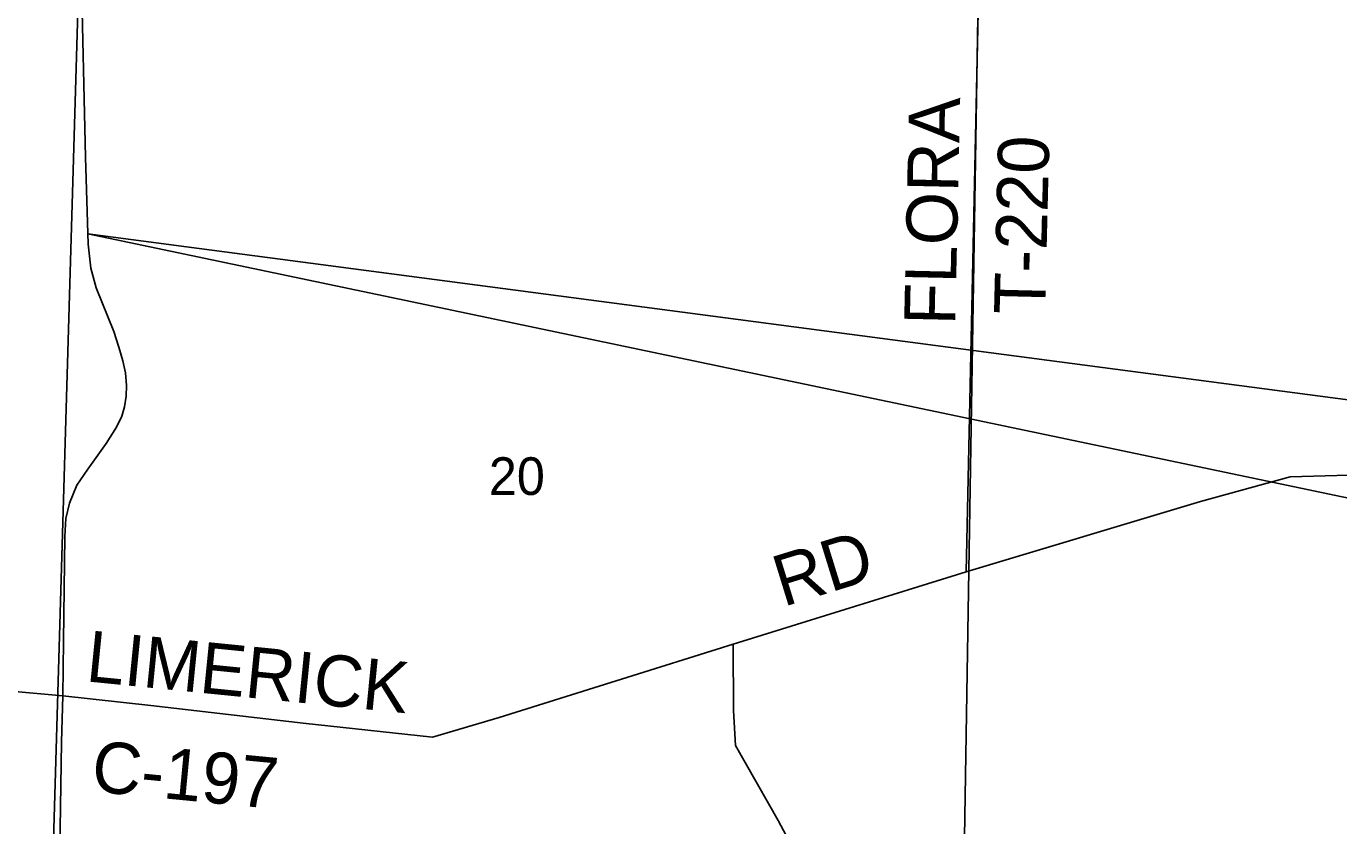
# Model space of a CAD drawing. Extents: x 0 to 34, y 0 to 22.
# Drawn here: x 3.441 to 4.9, y 16.557 to 17.445 of the extents above; entities that cross this region are included whole.
import ezdxf

# ---------------------------------------------------------------- set-up
doc = ezdxf.new("R2010")
doc.units = 0
for name, color, linetype in [('GM_X_County_Road', 7, 'Continuous'), ('GM_X_County_Road_Text', 7, 'Continuous'), ('GM_X_Section', 7, 'Continuous'), ('GM_X_Section_Text', 7, 'Continuous'), ('GM_X_State_Route', 7, 'Continuous'), ('GM_X_Township_Road', 7, 'Continuous'), ('GM_X_Township_Road_Text', 7, 'Continuous'), ('SH_Data', 7, 'Continuous')]:
    doc.layers.add(name, color=color, linetype=linetype)

msp = doc.modelspace()

# ---------------------------------------------------------------- linework, layer by layer
at = {"layer": 'GM_X_County_Road'}
for points in [[(3.0902, 16.9681), (3.0989, 16.9182), (3.1077, 16.7783), (3.1085, 16.7608), (3.1091, 16.7524), (3.1116, 16.7417), (3.1124, 16.7398), (3.1168, 16.7333), (3.1205, 16.7304), (3.1255, 16.7274), (3.1334, 16.7262), (3.3912, 16.7049), (3.4243, 16.7061), (3.4818, 16.701)], [(3.4818, 16.701), (3.5794, 16.6905), (3.7487, 16.6707), (3.8927, 16.6551), (3.9667, 16.6771), (4.2269, 16.7584), (4.486, 16.8389), (4.7465, 16.9172), (4.8464, 16.9445), (4.9885, 16.9486), (5.2393, 16.9438), (5.4858, 16.949)]]:
    msp.add_lwpolyline(points, dxfattribs=at)
at = {"layer": 'GM_X_Section'}
for points in [[(3.4982, 17.462), (3.4692, 16.4646), (2.4877, 16.4726), (2.5103, 17.4328), (2.5117, 17.4662)], [(4.4991, 17.4554), (4.4826, 16.453), (3.4692, 16.4646), (3.4982, 17.462)], [(5.5087, 17.4571), (5.4956, 16.4418), (4.4826, 16.453), (4.4991, 17.4554)]]:
    msp.add_lwpolyline(points, close=True, dxfattribs=at)
at = {"layer": 'GM_X_State_Route'}
msp.add_lwpolyline([(3.4739, 16.2421), (3.4802, 16.6496), (3.4818, 16.701), (3.4824, 16.762), (3.4837, 16.8781), (3.4849, 16.8983), (3.4891, 16.9153), (3.4973, 16.935), (3.5093, 16.953), (3.5297, 16.9814), (3.5413, 16.9996), (3.5472, 17.0118), (3.5503, 17.0222), (3.552, 17.0341), (3.5525, 17.0461), (3.5513, 17.0599), (3.5484, 17.0733), (3.544, 17.0886), (3.5384, 17.1058), (3.5187, 17.1545), (3.5129, 17.1763), (3.5097, 17.2028), (3.5068, 17.2998), (3.4971, 17.7208)], dxfattribs=at)
at = {"layer": 'GM_X_Township_Road'}
msp.add_line((4.486, 16.8389), (4.5096, 17.9519), dxfattribs=at)
msp.add_lwpolyline([(5.5412, 15.849), (5.3873, 16.0366), (5.2909, 16.1369), (5.2777, 16.144), (5.2615, 16.1488), (5.2562, 16.1504), (5.2509, 16.1531), (5.2324, 16.1576), (5.1579, 16.1763), (4.8499, 16.2614), (4.7668, 16.2912), (4.7336, 16.2989), (4.5333, 16.3094), (4.4196, 16.3955), (4.3211, 16.4799), (4.2769, 16.5627), (4.2296, 16.6459), (4.2272, 16.6847), (4.2269, 16.7584)], dxfattribs=at)
at = {"layer": 'SH_Data'}
msp.add_lwpolyline([(3.5095, 17.2146), (9.8001, 15.8963), (9.8001, 16.3863)], close=True, dxfattribs=at)

# ---------------------------------------------------------------- texts
at = {"layer": 'GM_X_County_Road_Text'}
for s, rotation, p in [('RD', 17.1766, (4.2825, 16.7997)), ('LIMERICK', 354.3034, (3.5062, 16.7173)), ('C-197', 354.4817, (3.5121, 16.5951))]:
    msp.add_text(s, height=0.05682, rotation=rotation, dxfattribs=at).set_placement(p)
at = {"layer": 'GM_X_Section_Text'}
msp.add_text('20', height=0.04186, rotation=0, dxfattribs=at).set_placement((3.9553, 16.9243))
at = {"layer": 'GM_X_Township_Road_Text'}
for s, rotation, p in [('FLORA', 88.7408, (4.4738, 17.1126)), ('T-220', 88.5957, (4.5737, 17.1244))]:
    msp.add_text(s, height=0.05682, rotation=rotation, dxfattribs=at).set_placement(p)

doc.saveas('drawing.dxf')
